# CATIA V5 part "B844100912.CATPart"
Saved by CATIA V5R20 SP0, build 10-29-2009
Part number: B844100912
Revision: 1
Definition: design
Nomenclature: B844100912
Source: made
Description: NOT SPECIFIED
Bounding box of the stored display mesh (mm): x -10 to 10, y -10 to 10, z -9 to 12
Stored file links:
  C:\Users\Utente\Desktop\3D-FILES-B844\3D files B844\B844100912.CATPart
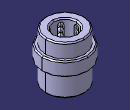
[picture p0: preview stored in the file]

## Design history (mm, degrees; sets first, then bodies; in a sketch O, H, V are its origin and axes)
Body1 "MANIFOLD_SOLID_BREP #38" (main body)
  Solid1: solid without history
Body2 "MANIFOLD_SOLID_BREP #76"
  Solid2: solid without history
Body3 "MANIFOLD_SOLID_BREP #114"
  Solid3: solid without history
Body4 "MANIFOLD_SOLID_BREP #152"
  Solid4: solid without history
Body5 "MANIFOLD_SOLID_BREP #190"
  Solid5: solid without history
Body6 "MANIFOLD_SOLID_BREP #228"
  Solid6: solid without history
Body7 "MANIFOLD_SOLID_BREP #266"
  Solid7: solid without history
Body8 "MANIFOLD_SOLID_BREP #304"
  Solid8: solid without history
Body9 "MANIFOLD_SOLID_BREP #1958"
  Solid9: solid without history
Body10 "MANIFOLD_SOLID_BREP #1996"
  Solid10: solid without history
Body11 "MANIFOLD_SOLID_BREP #2034"
  Solid11: solid without history
Body12 "MANIFOLD_SOLID_BREP #2072"
  Solid12: solid without history
Body13 "MANIFOLD_SOLID_BREP #2110"
  Solid13: solid without history
Body14 "MANIFOLD_SOLID_BREP #2148"
  Solid14: solid without history
Body15 "MANIFOLD_SOLID_BREP #2186"
  Solid15: solid without history
Body16 "MANIFOLD_SOLID_BREP #2224"
  Solid16: solid without history
Body17 "MANIFOLD_SOLID_BREP #2262"
  Solid17: solid without history
Body18 "MANIFOLD_SOLID_BREP #2300"
  Solid18: solid without history
Body19 "MANIFOLD_SOLID_BREP #2338"
  Solid19: solid without history
Body20 "MANIFOLD_SOLID_BREP #2376"
  Solid20: solid without history
Body21 "MANIFOLD_SOLID_BREP #2414"
  Solid21: solid without history
Body22 "MANIFOLD_SOLID_BREP #2452"
  Solid22: solid without history
Body23 "MANIFOLD_SOLID_BREP #2490"
  Solid23: solid without history
Body24 "MANIFOLD_SOLID_BREP #2528"
  Solid24: solid without history
Body25 "MANIFOLD_SOLID_BREP #2566"
  Solid25: solid without history
Body26 "MANIFOLD_SOLID_BREP #2604"
  Solid26: solid without history
Body27 "MANIFOLD_SOLID_BREP #2642"
  Solid27: solid without history
Body28 "MANIFOLD_SOLID_BREP #2680"
  Solid28: solid without history
Body29 "MANIFOLD_SOLID_BREP #2718"
  Solid29: solid without history
Body30 "MANIFOLD_SOLID_BREP #2756"
  Solid30: solid without history
Body31 "MANIFOLD_SOLID_BREP #2794"
  Solid31: solid without history
Body32 "MANIFOLD_SOLID_BREP #2832"
  Solid32: solid without history
Body33 "MANIFOLD_SOLID_BREP #2870"
  Solid33: solid without history
Body34 "MANIFOLD_SOLID_BREP #2908"
  Solid34: solid without history
Body35 "MANIFOLD_SOLID_BREP #2946"
  Solid35: solid without history
Body36 "MANIFOLD_SOLID_BREP #2984"
  Solid36: solid without history
Body37 "MANIFOLD_SOLID_BREP #3022"
  Solid37: solid without history
Body38 "MANIFOLD_SOLID_BREP #3060"
  Solid38: solid without history
Body39 "MANIFOLD_SOLID_BREP #3098"
  Solid39: solid without history
Body40 "MANIFOLD_SOLID_BREP #3136"
  Solid40: solid without history
Body41 "MANIFOLD_SOLID_BREP #3174"
  Solid41: solid without history
Body42 "MANIFOLD_SOLID_BREP #3212"
  Solid42: solid without history
Body43 "MANIFOLD_SOLID_BREP #3250"
  Solid43: solid without history
Body44 "MANIFOLD_SOLID_BREP #3288"
  Solid44: solid without history
Body45 "MANIFOLD_SOLID_BREP #3326"
  Solid45: solid without history
Body46 "MANIFOLD_SOLID_BREP #3364"
  Solid46: solid without history
Body47 "MANIFOLD_SOLID_BREP #3402"
  Solid47: solid without history
Body48 "MANIFOLD_SOLID_BREP #3440"
  Solid48: solid without history
Body49 "MANIFOLD_SOLID_BREP #3478"
  Solid49: solid without history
